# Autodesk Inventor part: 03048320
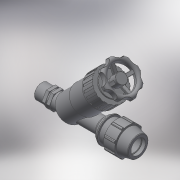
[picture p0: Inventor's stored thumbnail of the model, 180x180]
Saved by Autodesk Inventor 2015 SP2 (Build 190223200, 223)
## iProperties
Created: 2017-02
Part Number: 03048320
Material: Generic
Description: PLASSON ANGLE SEAT VALVE 32-1"
Document SubType Name: Modeling
Designer: KIM
Mass: 524.197 g
Surface Area: 881.032 cm^2
Volume: 524.197 cm^3
Density: 1 g/cm^3
Appearance: Default
Author: KIM
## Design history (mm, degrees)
derived "03048-03948.ipt"
feature "Solid1::03048-03948.ipt"
tag "TaggingFeature1"
body "Solid1"
other parameters: "d2" = 32, "d4" = 8.83333, "d5" = 21.2, "d7" = 64, "d11" = 3.02857, "d13" = 120 deg, "d14" = 44.8, "d15" = 12 deg, "d16" = 55.68, "d18" = 1.6, "d19" = 35 deg, "d20" = 17.5 deg, "d21" = 59.52, "d23" = 0, "d25" = 360 deg, "d27" = 1.28, "d33" = 0.64, "d42" = 25.44, "d43" = 1.92, "d46" = 0.96, "d67" = 48, "d96" = 5.3, "d128" = 212, "d159" = 2, "d165" = 126, "d167" = 75.6, "d168" = 22.68, "d169" = 22.68, "d170" = 90 deg, "d171" = 70 deg, "d172" = 18.144, "d173" = 52.92, "d174" = 52.92, "d175" = 68.04, "d176" = 135 deg, "d177" = 60.48, "d178" = 56.7, "d179" = 31.5, "d180" = 126, "d182" = 18.144, "d183" = 49.896, "d190" = 45 deg, "d191" = 42.4, "d192" = 2.8, "d193" = 4.52, "d194" = 2.26, "d195" = 65.9988, "d198" = 0, "d199" = 28.35, "d200" = 113, "d204" = 360 deg, "d209" = 0, "d213" = 3.78, "d216" = 360 deg, "d220" = 64.26, "d221" = 3.39, "d222" = 3.39, "d223" = 6.78, "d227" = 3.39, "d229" = 0, "d230" = 0.7, "d232" = 360 deg, "d234" = 0.7, "d235" = 0.7, "d237" = 360 deg, "d239" = 1.12, "d241" = 0.7, "d249" = 33.249, "d250" = 45 deg, "d251" = 25.6, "d252" = 212, "d254" = 6.66667, "d255" = 3.33333, "d256" = 34, "d258" = 0, "d260" = 0, "d261" = 0.66498, "d265" = 0, "d_" = 32, "E_" = 64, "H_" = 212, "d224" = 113, "G_" = 33.249, "d202" = 68.04, "d214" = 75.6, "d218" = 75.6, "d225" = 75.6, "d226" = 52.92
